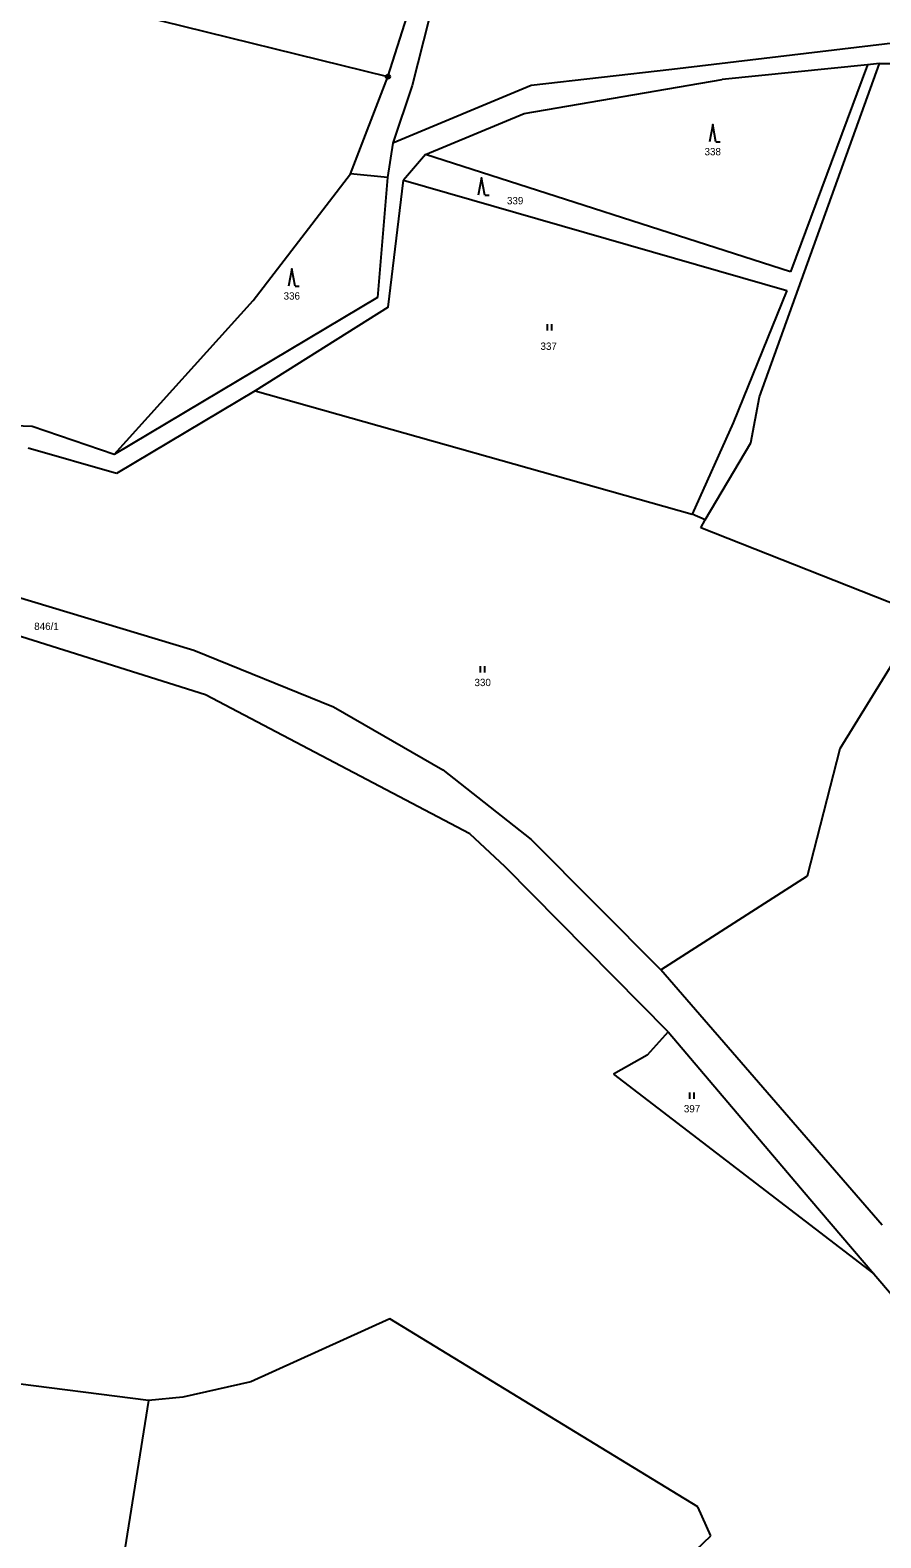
# Model space of a CAD drawing. Extents: x -739410 to -735662, y -942282 to -940043.
# Drawn here: x -736703.1 to -736506.1, y -941395 to -941045.7 of the extents above; entities that cross this region are included whole.
import ezdxf
from ezdxf.enums import TextEntityAlignment as Align

# ---------------------------------------------------------------- set-up
doc = ezdxf.new("R2010")
doc.units = 0
doc.header["$LTSCALE"] = 0.68
for name, color, linetype, lineweight in [('1', 7, 'Continuous', 25), ('3', 7, 'Continuous', 25), ('8', 7, 'Continuous', 25)]:
    doc.layers.add(name, color=color, linetype=linetype, lineweight=lineweight)
doc.layers.add('2', color=7, linetype='Continuous')

msp = doc.modelspace()

# ---------------------------------------------------------------- linework, layer by layer
at = {"layer": '1'}
for p, q in [((-736604.16, -941016.9), (-736614.66, -941058.57)), ((-736620.26, -941056.51), (-736677.98, -941042.34)), ((-736620.26, -941056.51), (-736615.78, -941042.46)), ((-736502.03, -941048.63), (-736554.54, -941054.86)), ((-736554.54, -941054.86), (-736587.06, -941058.52)), ((-736509.2, -941053.75), (-736542.85, -941057.15)), ((-736534.21, -941130.69), (-736506.36, -941053.48)), ((-736509.2, -941053.75), (-736527.04, -941101.71)), ((-736506.36, -941053.48), (-736509.2, -941053.75)), ((-736506.36, -941053.48), (-736491.43, -941053.49)), ((-736628.92, -941079), (-736620.26, -941056.51)), ((-736587.06, -941058.52), (-736619.17, -941071.91)), ((-736614.66, -941058.57), (-736619.17, -941071.91)), ((-736588.7, -941065.02), (-736542.85, -941057.15)), ((-736611.56, -941074.57), (-736588.7, -941065.02)), ((-736619.17, -941071.91), (-736620.38, -941079.87)), ((-736651.49, -941108.34), (-736628.92, -941079)), ((-736620.38, -941079.87), (-736628.92, -941079)), ((-736620.38, -941079.87), (-736622.65, -941107.68)), ((-736620.19, -941109.91), (-736616.63, -941080.47)), ((-736616.63, -941080.47), (-736527.83, -941106.08)), ((-736622.65, -941107.68), (-736683.7, -941144.07)), ((-736683.7, -941144.07), (-736651.49, -941108.34)), ((-736527.83, -941106.08), (-736540.33, -941136.72)), ((-736620.19, -941109.91), (-736651, -941129.25)), ((-736651, -941129.25), (-736683.12, -941148.47)), ((-736651, -941129.25), (-736549.79, -941157.86)), ((-736536.18, -941141.33), (-736534.21, -941130.69)), ((-736702.69, -941137.57), (-736748.64, -941135.56)), ((-736683.7, -941144.07), (-736702.69, -941137.57)), ((-736540.33, -941136.72), (-736549.79, -941157.86)), ((-736683.12, -941148.47), (-736703.6, -941142.56)), ((-736546.77, -941159.14), (-736536.18, -941141.33)), ((-736546.77, -941159.14), (-736549.79, -941157.86)), ((-736547.76, -941161), (-736546.77, -941159.14)), ((-736496.53, -941181.32), (-736547.76, -941161)), ((-736662.54, -941199.72), (-736779.98, -941162.78)), ((-736712.29, -941175.17), (-736665.25, -941189.38)), ((-736515.53, -941212.13), (-736496.53, -941181.32)), ((-736665.25, -941189.38), (-736632.91, -941202.49)), ((-736601.26, -941231.9), (-736662.54, -941199.72)), ((-736632.91, -941202.49), (-736607.55, -941217.08)), ((-736523.07, -941241.63), (-736515.53, -941212.13)), ((-736607.55, -941217.08), (-736587.12, -941233.25)), ((-736593.13, -941239.54), (-736601.26, -941231.9)), ((-736587.12, -941233.25), (-736557.04, -941263.38)), ((-736555.33, -941277.78), (-736593.13, -941239.54)), ((-736557.04, -941263.38), (-736523.07, -941241.63)), ((-736505.81, -941322.6), (-736557.04, -941263.38)), ((-736555.33, -941277.78), (-736560.25, -941283.2)), ((-736555.33, -941277.78), (-736522.51, -941316.48)), ((-736560.25, -941283.2), (-736568, -941287.57)), ((-736568, -941287.57), (-736507.71, -941333.83)), ((-736522.51, -941316.48), (-736507.71, -941333.83)), ((-736507.71, -941333.83), (-736465.43, -941383.41)), ((-736619.82, -941344.25), (-736652.06, -941358.89)), ((-736548.49, -941387.85), (-736619.82, -941344.25)), ((-736675.76, -941363.15), (-736709.59, -941358.88)), ((-736652.06, -941358.89), (-736667.79, -941362.39)), ((-736675.76, -941363.15), (-736681.22, -941397.57)), ((-736667.79, -941362.39), (-736675.76, -941363.15)), ((-736545.43, -941394.51), (-736548.49, -941387.85)), ((-736602.45, -941448.49), (-736545.43, -941394.51))]:
    msp.add_line(p, q, dxfattribs=at)
msp.add_lwpolyline([(-736527.04, -941101.71), (-736611.56, -941074.57), (-736616.63, -941080.47)], dxfattribs=at)
at = {"layer": '3'}
for p, q in [((-736544.28, -941071.6), (-736543.284, -941071.6)), ((-736597.83, -941083.95), (-736596.834, -941083.95)), ((-736641.79, -941105.03), (-736640.794, -941105.03)), ((-736583.331, -941115.31), (-736583.331, -941113.81)), ((-736582.33, -941115.31), (-736582.33, -941113.81)), ((-736598.831, -941194.57), (-736598.831, -941193.07)), ((-736597.83, -941194.57), (-736597.83, -941193.07)), ((-736550.331, -941293.31), (-736550.331, -941291.81)), ((-736549.33, -941293.31), (-736549.33, -941291.81))]:
    msp.add_line(p, q, dxfattribs=at)
for points in [[(-736544.28, -941071.6), (-736545.03, -941067.6), (-736545.78, -941071.6)], [(-736597.83, -941083.95), (-736598.58, -941079.95), (-736599.33, -941083.95)], [(-736641.79, -941105.03), (-736642.54, -941101.03), (-736643.29, -941105.03)]]:
    msp.add_lwpolyline(points, dxfattribs=at)
at = {"layer": '8'}
for radius in [0.5, 0.0303]:
    msp.add_circle((-736620.26, -941056.5099), radius, dxfattribs=at)

# ---------------------------------------------------------------- texts
at = {"layer": '2'}
for s, p in [('338', (-736545.029, -941074.725)), ('339', (-736590.799, -941086.085)), ('336', (-736642.539, -941108.155)), ('337', (-736583.029, -941119.795)), ('846/1', (-736699.36, -941184.685)), ('330', (-736598.319, -941197.695)), ('397', (-736549.819, -941296.435))]:
    msp.add_text(s, height=1.7, dxfattribs=at).set_placement(p, align=Align.CENTER)

doc.saveas('drawing.dxf')
